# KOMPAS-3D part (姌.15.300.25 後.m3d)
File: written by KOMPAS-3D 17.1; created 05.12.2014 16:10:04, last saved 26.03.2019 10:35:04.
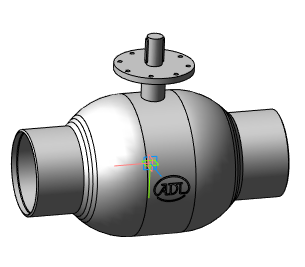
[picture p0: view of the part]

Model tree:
1. Операция без истории:5  (labels: Сталь 20  ГОСТ 1050-88)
